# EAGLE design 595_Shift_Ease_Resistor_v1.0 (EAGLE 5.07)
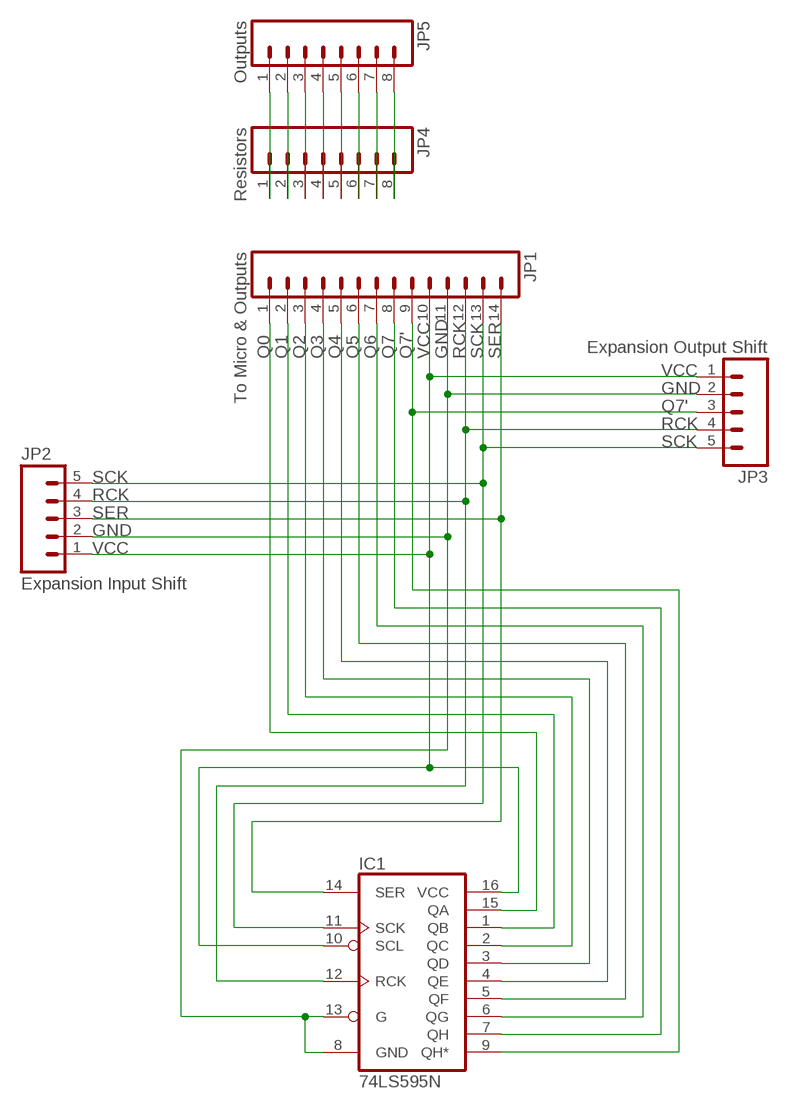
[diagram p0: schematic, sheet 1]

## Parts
IC1  74LS595N  [DIL16]
JP1  To Micro & Outputs  M141X14_FH  [1X14_FH]
JP2  Expansion Input Shift  M051X05_M_H  [1X05_M_H]
JP3  Expansion Output Shift  M051X05_F_H  [1X05_F_H]
JP4  Resistors  M08  [1X08]
JP5  Outputs  M08  [1X08]

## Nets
GND: IC1.8(GND) IC1.13(G) JP1.11 JP2.2 JP3.2
N$3: JP4.1 JP5.1
N$4: JP4.2 JP5.2
N$5: JP4.3 JP5.3
N$6: JP4.4 JP5.4
N$7: JP4.5 JP5.5
N$8: JP4.6 JP5.6
N$9: JP4.7 JP5.7
N$10: JP4.8 JP5.8
Q0: IC1.15(QA) JP1.1
Q1: IC1.1(QB) JP1.2
Q2: IC1.2(QC) JP1.3
Q3: IC1.3(QD) JP1.4
Q4: IC1.4(QE) JP1.5
Q5: IC1.5(QF) JP1.6
Q6: IC1.6(QG) JP1.7
Q7: IC1.7(QH) JP1.8
Q7': IC1.9(QH*) JP1.9 JP3.3
RCK: IC1.12(RCK) JP1.12 JP2.4 JP3.4
SCK: IC1.11(SCK) JP1.13 JP2.5 JP3.5
SER: IC1.14(SER) JP1.14 JP2.3
VCC: IC1.10(SCL) IC1.16(VCC) JP1.10 JP2.1 JP3.1

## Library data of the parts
IC1 = SparkFun:74*595: 8-bit SHIFT REGISTER, output latch
JP1 = SparkFun:M14: Header 14 Standard 14-pin 0.1" header. Use with straight break away headers (SKU : PRT-00116), right angle break away headers (PRT-00553), swiss pins (PRT-00743), machine pins (PRT-00117), and female headers (PRT-00115).
JP2 JP3 = SparkFun:M05: Header 5 Standard 5-pin 0.1" header. Use with straight break away headers (SKU : PRT-00116), right angle break away headers (PRT-00553), swiss pins (PRT-00743), machine pins (PRT-00117), and female headers (PRT-00115). Molex polarized connector foot print use with SKU : PRT-08230 with associated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
JP4 JP5 = SparkFun:M08: Header 8 Standard 8-pin 0.1" header. Use with straight break away headers (SKU : PRT-00116), right angle break away headers (PRT-00553), swiss pins (PRT-00743), machine pins (PRT-00117), and female headers (PRT-00115).

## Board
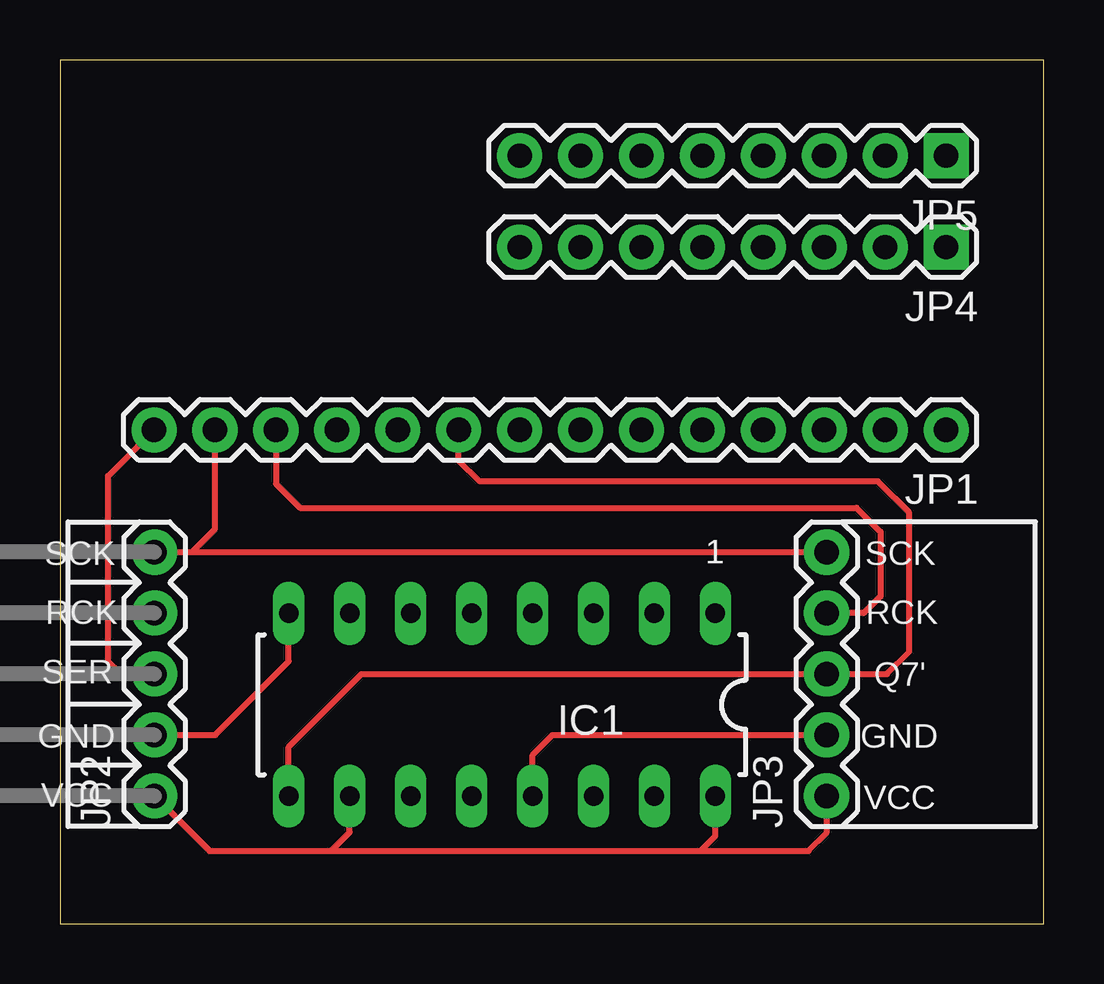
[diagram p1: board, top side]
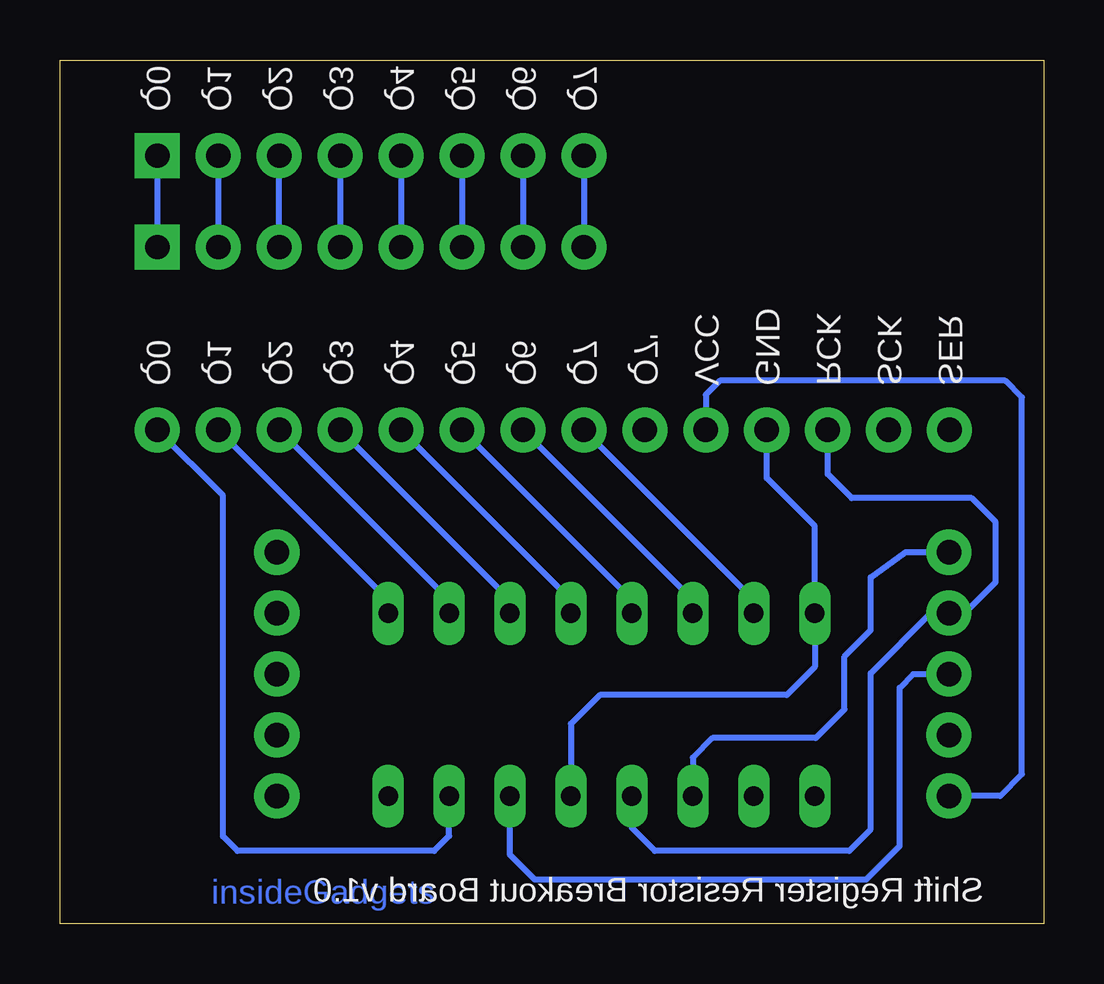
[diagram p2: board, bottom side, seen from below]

Size 41 x 36 mm. Coordinates in mm from the lower left corner, seen from the top.
Outline: 0,0 41,0 41,36 0,36 0,0
Copper layers (1*16): Top 0.035mm / dielectric 1.5mm / Bottom 0.035mm
Design rules "default": minimum track width 10mil, minimum drill 24mil, track to track 8mil, track to pad 8mil, pad to pad 8mil, via to via 8mil, smd to smd 8mil, copper to edge 40mil, drill to drill 8mil, minimum pad ring 10mil, minimum via ring 8mil, stop-mask expansion 4mil, vias tented up to drill 0mil, thermal gap 10mil

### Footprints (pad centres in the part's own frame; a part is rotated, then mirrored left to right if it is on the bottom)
DIL16 = drill 0.813 long: 1 -8.89,-3.81; 2 -6.35,-3.81; 3 -3.81,-3.81; 4 -1.27,-3.81; 5 1.27,-3.81; 6 3.81,-3.81; 7 6.35,-3.81; 8 8.89,-3.81; 9 8.89,3.81; 10 6.35,3.81; 11 3.81,3.81; 12 1.27,3.81; 13 -1.27,3.81; 14 -3.81,3.81; 15 -6.35,3.81; 16 -8.89,3.81
1X14_FH = drill 1.016 pad 1.88 round: 1 0,0; 2 2.54,0; 3 5.08,0; 4 7.62,0; 5 10.16,0; 6 12.7,0; 7 15.24,0; 8 17.78,0; 9 20.32,0; 10 22.86,0; 11 25.4,0; 12 27.94,0; 13 30.48,0; 14 33.02,0
1X05_M_H = drill 1.016 pad 1.88 round: 1 0,0; 2 2.54,0; 3 5.08,0; 4 7.62,0; 5 10.16,0
1X05_F_H = drill 1.016 pad 1.88 round: 1 0,0; 2 2.54,0; 3 5.08,0; 4 7.62,0; 5 10.16,0
1X08 = drill 1.016 pad 1.88 square: 1 0,0 | drill 1.016 pad 1.88 round: 2 2.54,0; 3 5.08,0; 4 7.62,0; 5 10.16,0; 6 12.7,0; 7 15.24,0; 8 17.78,0

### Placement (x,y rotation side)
IC1  18.43,9.12 180 top
JP1  36.94,20.58 180 top
JP2  3.94,5.32 90 top
JP3  31.96,5.32 90 top
JP4  36.94,28.2 180 top
JP5  36.94,32.01 180 top

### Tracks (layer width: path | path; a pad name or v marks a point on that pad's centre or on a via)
GND
  Top 0.254: JP2.2 6.47,7.86 9.54,10.93 IC1.8 | IC1.13 19.7,7.03 20.53,7.86 JP3.2
  Bottom 0.254: JP1.11 11.54,18.57 9.54,16.57 IC1.8 9.54,10.69 10.7,9.53 18.5,9.53 19.7,8.33 IC1.13
N$3
  Bottom 0.254: JP5.1 JP4.1
N$4
  Bottom 0.254: JP5.2 JP4.2
N$5
  Bottom 0.254: JP4.3 JP5.3
N$6
  Bottom 0.254: JP5.4 JP4.4
N$7
  Bottom 0.254: JP5.5 JP4.5
N$8
  Bottom 0.254: JP5.6 JP4.6
N$9
  Bottom 0.254: JP5.7 JP4.7
N$10
  Bottom 0.254: JP5.8 JP4.8
Q0
  Bottom 0.254: JP1.1 34.2,17.84 34.2,3.63 33.6,3.03 25.4,3.03 24.78,3.65 IC1.15
Q1
  Bottom 0.254: JP1.2 27.32,13.5 IC1.1
Q2
  Bottom 0.254: JP1.3 24.78,13.5 IC1.2
Q3
  Bottom 0.254: JP1.4 22.24,13.5 IC1.3
Q4
  Bottom 0.254: JP1.5 19.7,13.5 IC1.4
Q5
  Bottom 0.254: JP1.6 17.16,13.5 IC1.5
Q6
  Bottom 0.254: JP1.7 14.62,13.5 IC1.6
Q7
  Bottom 0.254: JP1.8 12.08,13.5 IC1.7
Q7'
  Top 0.254: JP1.9 16.62,19.31 17.5,18.43 34.1,18.43 35.4,17.13 35.4,11.33 34.47,10.4 JP3.3 12.57,10.4 9.54,7.37 IC1.9
RCK
  Top 0.254: JP1.12 9,18.33 10,17.33 33.2,17.33 34.2,16.33 34.2,13.63 33.51,12.94 JP3.4
  Bottom 0.254: JP1.12 9,18.73 8,17.73 3,17.73 2,16.73 2,14.23 3.29,12.94 JP2.4 4.69,12.94 7.2,10.43 7.2,3.93 8.1,3.03 16.2,3.03 17.16,3.99 IC1.12
SCK
  Top 0.254: JP2.5 5.5,15.48 | 5.5,15.48 JP3.5 | JP1.13 6.46,16.44 5.5,15.48
  Bottom 0.254: JP2.5 5.75,15.48 7.2,14.43 7.2,12.23 8.3,11.13 8.3,8.93 9.5,7.73 13.8,7.73 14.62,6.91 IC1.11
SER
  Top 0.254: JP1.14 2,18.66 2,10.93 2.53,10.4 JP2.3
  Bottom 0.254: JP2.3 5.43,10.4 6,9.83 6,3.23 7.4,1.83 21.2,1.83 22.24,2.87 IC1.14
VCC
  Top 0.254: JP2.1 6.23,3.03 11.3,3.03 | 11.3,3.03 26.7,3.03 | 26.7,3.03 31.2,3.03 31.96,3.79 JP3.1 | IC1.10 12.08,3.81 11.3,3.03 | IC1.16 27.32,3.65 26.7,3.03
  Bottom 0.254: JP1.10 14.08,22.05 13.5,22.63 1.6,22.63 0.9,21.93 0.9,6.23 1.81,5.32 JP2.1

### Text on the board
Bottom: insideGadgets
tPlace: SCK | SCK | 1 | RCK | RCK | SER | Q7' | GND | GND | VCC | VCC
bPlace: Q7 | Q6 | Q5 | Q4 | Q3 | Q2 | Q1 | Q0 | SER | SCK | RCK | GND | VCC | Q7' | Q7 | Q6 | Q5 | Q4 | Q3 | Q2 | Q1 | Q0 | Shift Register Resistor Breakout Board v1.0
